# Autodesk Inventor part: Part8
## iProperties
Shininess: 64.0
Length Units: 11269
Angle Units: 11279
Time Units: 11290
Mass Units: 11283
Length Display Precision: 3
Angle Display Precision: 2
Compacted: True
Part Number: Part8
Document SubType Name: Modeling
Created: 2002-12
Designer: deepak
Density: 1 g/cm^3
Density: 0.0
Volumn: 0.0
Area: 0.0
PropertySet Name: Model Information
Control State: 0
Master: False
Checked Out: False
Author: deepak
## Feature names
1. Extrusion1
2. Extrusion2
3. Rectangular Pattern1
4. Shell2
5. Split2
